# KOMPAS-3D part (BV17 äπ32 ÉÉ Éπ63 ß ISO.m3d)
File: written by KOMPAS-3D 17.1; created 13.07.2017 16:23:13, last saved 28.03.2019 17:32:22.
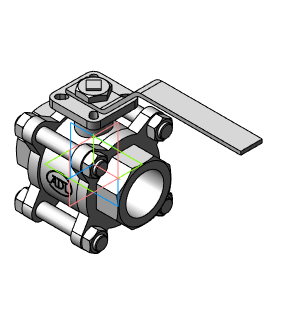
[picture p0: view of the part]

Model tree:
1. Операция без истории:2  (labels: Сталь 20  ГОСТ 1050-88)

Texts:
  DISO1
  DISO2
  BV17 Ду8 1/4" Ру63 с ISO
  BV17 Ду8 СС Ру63 с ISO
  BV17 Ду10 3/8" Ру63 с ISO
  BV17 Ду10 СС Ру63 с ISO
  BV17 Ду15 1/2" Ру63 с ISO
  BV17 Ду15 СС Ру63 с ISO
  BV17 Ду15 ФФ Ру40 с ISO
  BV17 Ду20 3/4" Ру63 с ISO
  BV17 Ду20 СС Ру40 с ISO
  BV17 Ду20 ФФ Ру40 с ISO
  BV17 Ду25 1" Ру63 с ISO
  BV17 Ду25 СС Ру63 с ISO
  BV17 Ду25 ФФ Ру40 с ISO
  BV17 Ду32 1 1/4" Ру63 с ISO
  BV17 Ду32 СС Ру63 с ISO
  BV17 Ду32 ФФ Ру40 с ISO
  BV17 Ду40 1 1/2" Ру63 с ISO
  BV17 Ду40 СС Ру63 с ISO
  BV17 Ду40 ФФ Ру40 с ISO
  BV17 Ду50 2" Ру63 с ISO
  BV17 Ду50 СС Ру63 с ISO
  BV17 Ду50 ФФ Ру40 с ISO
  BV17 Ду65 2 1/2" Ру40 с ISO
  BV17 Ду65 СС Ру40 с ISO
  BV17 Ду65 ФФ Ру40 с ISO
  BV17 Ду80 3" Ру40 с ISO
  BV17 Ду80 СС Ру40 с ISO
  BV17 Ду80 ФФ Ру40 с ISO
  BV17 Ду100 4" Ру40 с ISO
  BV17 Ду100 СС Ру40 с ISO
  BV17 Ду100 ФФ Ру40 с ISO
